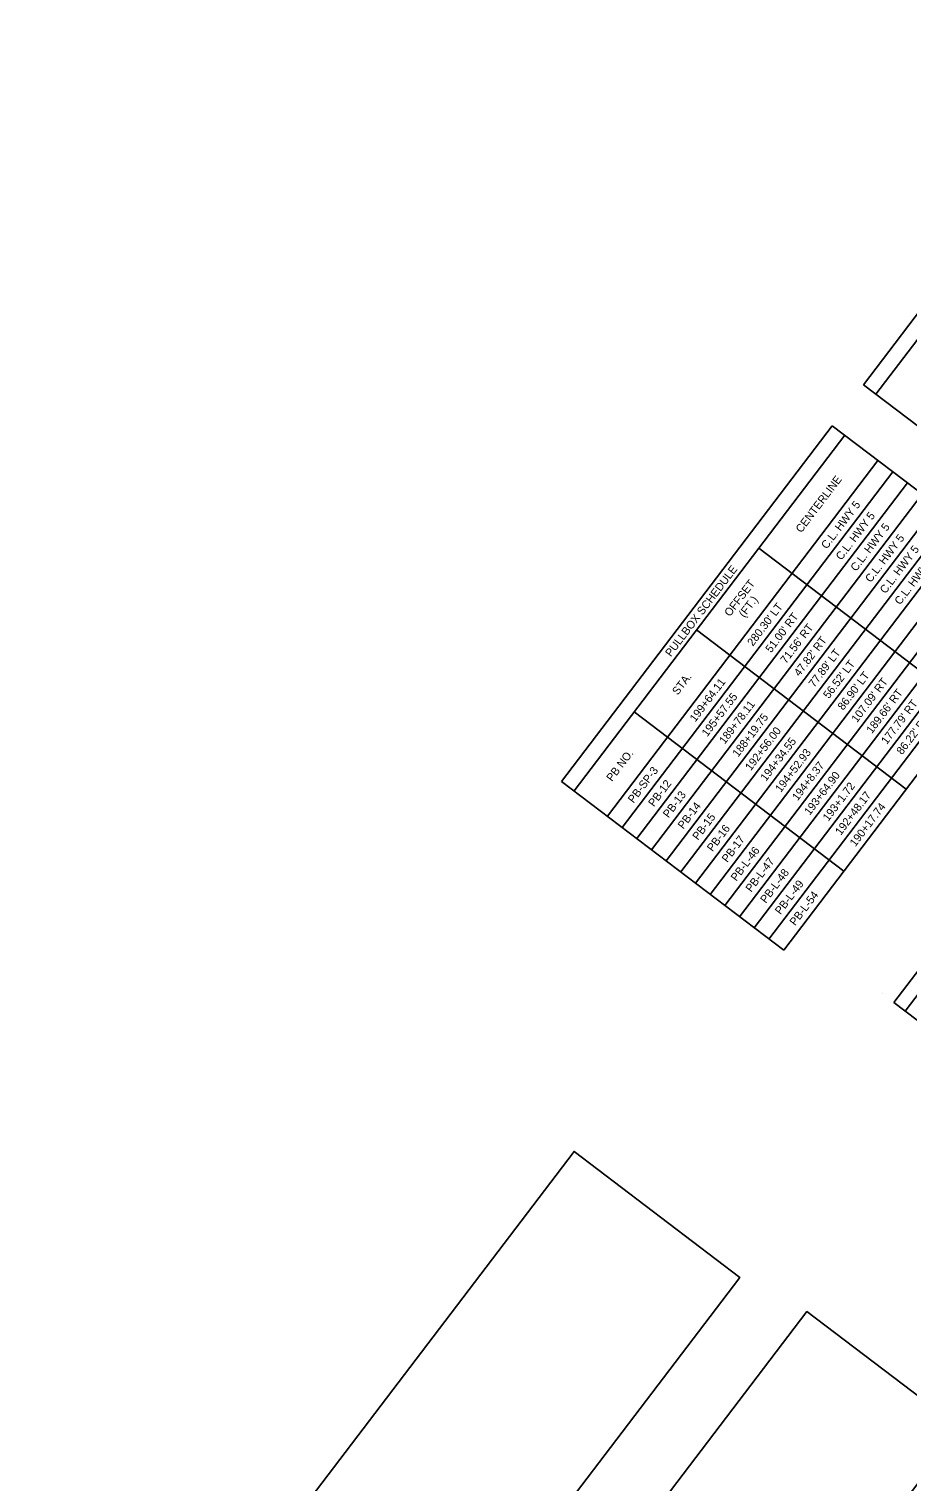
# Model space of a CAD drawing. Extents: x 1289840 to 1300285, y 220865 to 232462.
# Drawn here: x 1298111 to 1298836, y 230702 to 231900 of the extents above; entities that cross this region are included whole.
import ezdxf

# ---------------------------------------------------------------- set-up
doc = ezdxf.new("R2010")
doc.units = 0
doc.layers.add('Default', color=7, linetype='Continuous')
doc.layers.add('R_No Plot', color=7, linetype='Continuous')

msp = doc.modelspace()

# ---------------------------------------------------------------- linework, layer by layer
at = {"layer": 'Default'}
for p, q in [((1298799.2, 231606.6), (1299022.3, 231900)), ((1298809.4, 231598.8), (1299032.5, 231892.2)), ((1298982.2, 231467.4), (1298799.2, 231606.6)), ((1298550.4, 231279.5), (1298773.5, 231572.8)), ((1298956.5, 231433.7), (1298773.5, 231572.8)), ((1298560.7, 231271.7), (1298783.8, 231565)), ((1298588.2, 231250.8), (1298811.2, 231544.2)), ((1298600.3, 231241.6), (1298823.4, 231534.9)), ((1298612.4, 231232.4), (1298835.5, 231525.7)), ((1298624.5, 231223.2), (1298847.6, 231516.5)), ((1298636.6, 231214), (1298859.7, 231507.3)), ((1298648.7, 231204.8), (1298871.8, 231498.1)), ((1298660.8, 231195.5), (1298883.9, 231488.9)), ((1298824.4, 231097.2), (1299122.2, 231488.8)), ((1298672.9, 231186.3), (1298896, 231479.7)), ((1298833.7, 231090.1), (1299131.5, 231481.7)), ((1298685, 231177.1), (1298908.1, 231470.5)), ((1298885.7, 231340.5), (1298713, 231471.9)), ((1298697.1, 231167.9), (1298920.2, 231461.3)), ((1298709.2, 231158.7), (1298932.3, 231452.1)), ((1298721.3, 231149.5), (1298944.4, 231442.9)), ((1298733.5, 231140.3), (1298956.5, 231433.7)), ((1298834.4, 231273), (1298661.6, 231404.4)), ((1298783, 231205.5), (1298610.3, 231336.9)), ((1298733.5, 231140.3), (1298550.4, 231279.5)), ((1298908.2, 231033.4), (1298824.4, 231097.2))]:
    msp.add_line(p, q, dxfattribs=at)
at = {"layer": 'R_No Plot'}
for p, q in [((1298799.2, 231606.6), (1298799.2, 231606.6)), ((1298550.4, 231279.5), (1298550.4, 231279.5)), ((1298815.1, 231104.2), (1298815.1, 231104.2))]:
    msp.add_line(p, q, dxfattribs=at)
for points in [[(1298248.1, 230279.6), (1298697.3, 230870.4), (1298560.7, 230974.3), (1298111.5, 230383.5)], [(1298424.8, 230149.1), (1298878.9, 230746.3), (1298752.7, 230842.3), (1298298.6, 230245)]]:
    msp.add_lwpolyline(points, close=True, dxfattribs=at)

# ---------------------------------------------------------------- texts
at = {"layer": 'Default'}
for s, p in [('CENTERLINE', (1298748, 231484)), ('C.L. HWY 5', (1298769, 231470.6)), ('C.L. HWY 5', (1298781.1, 231461.4)), ('C.L. HWY 5', (1298793.2, 231452.2)), ('C.L. HWY 5', (1298805.3, 231443)), ('C.L. HWY 5', (1298817.4, 231433.8)), ('C.L. HWY 5', (1298829.5, 231424.6)), ('PULLBOX SCHEDULE', (1298640.5, 231381.8)), ('OFFSET', (1298689.2, 231414.9)), (' (FT.)', (1298699.6, 231412.2)), ("280.30' LT", (1298708.1, 231390.5)), ("51.00' RT", (1298723.1, 231385.1)), ("71.56' RT", (1298735.4, 231376.1)), ("47.82' RT", (1298746.5, 231365.6)), ("77.89' LT", (1298758.7, 231356.5)), ("56.52' LT", (1298770.7, 231347.2)), ("86.90' LT", (1298782.6, 231337.7)), ('STA.', (1298646.2, 231350.2)), ('199+64.11', (1298660.6, 231328)), ("107.09' RT", (1298793.9, 231327.5)), ("189.66' RT", (1298806.2, 231318.4)), ('195+57.55', (1298670.5, 231315.9)), ('189+78.11', (1298684.9, 231309.7)), ("177.79' RT", (1298818.5, 231309.5)), ('188+19.75', (1298695.9, 231299)), ("86.22' RT", (1298831.1, 231301)), ('192+56.00', (1298706.4, 231287.8)), ('194+34.55', (1298718.9, 231279.1)), ('194+52.93', (1298731.1, 231269.9)), ('PB NO.', (1298592, 231278.9)), ('194+8.37', (1298745, 231263.1)), ('PB-SP-3', (1298609.7, 231261.1)), ('193+64.90', (1298755, 231251.1)), ('PB-12', (1298626.5, 231258.1)), ('PB-13', (1298638.6, 231248.9)), ('193+1.72', (1298770.3, 231246.1)), ('192+48.17', (1298780.6, 231234.6)), ('PB-14', (1298650.8, 231239.7)), ('190+17.74', (1298792.6, 231225.2)), ('PB-15', (1298662.9, 231230.5)), ('PB-16', (1298674.9, 231221.1)), ('PB-17', (1298687.1, 231212.1)), ('PB-L-46', (1298694.5, 231196.7)), ('PB-L-47', (1298706.7, 231187.7)), ('PB-L-48', (1298718.8, 231178.5)), ('PB-L-49', (1298730.9, 231169.2)), ('PB-L-54', (1298743, 231160))]:
    msp.add_text(s, height=6.6, rotation=52.7501, dxfattribs=at).set_placement(p)

doc.saveas('drawing.dxf')
